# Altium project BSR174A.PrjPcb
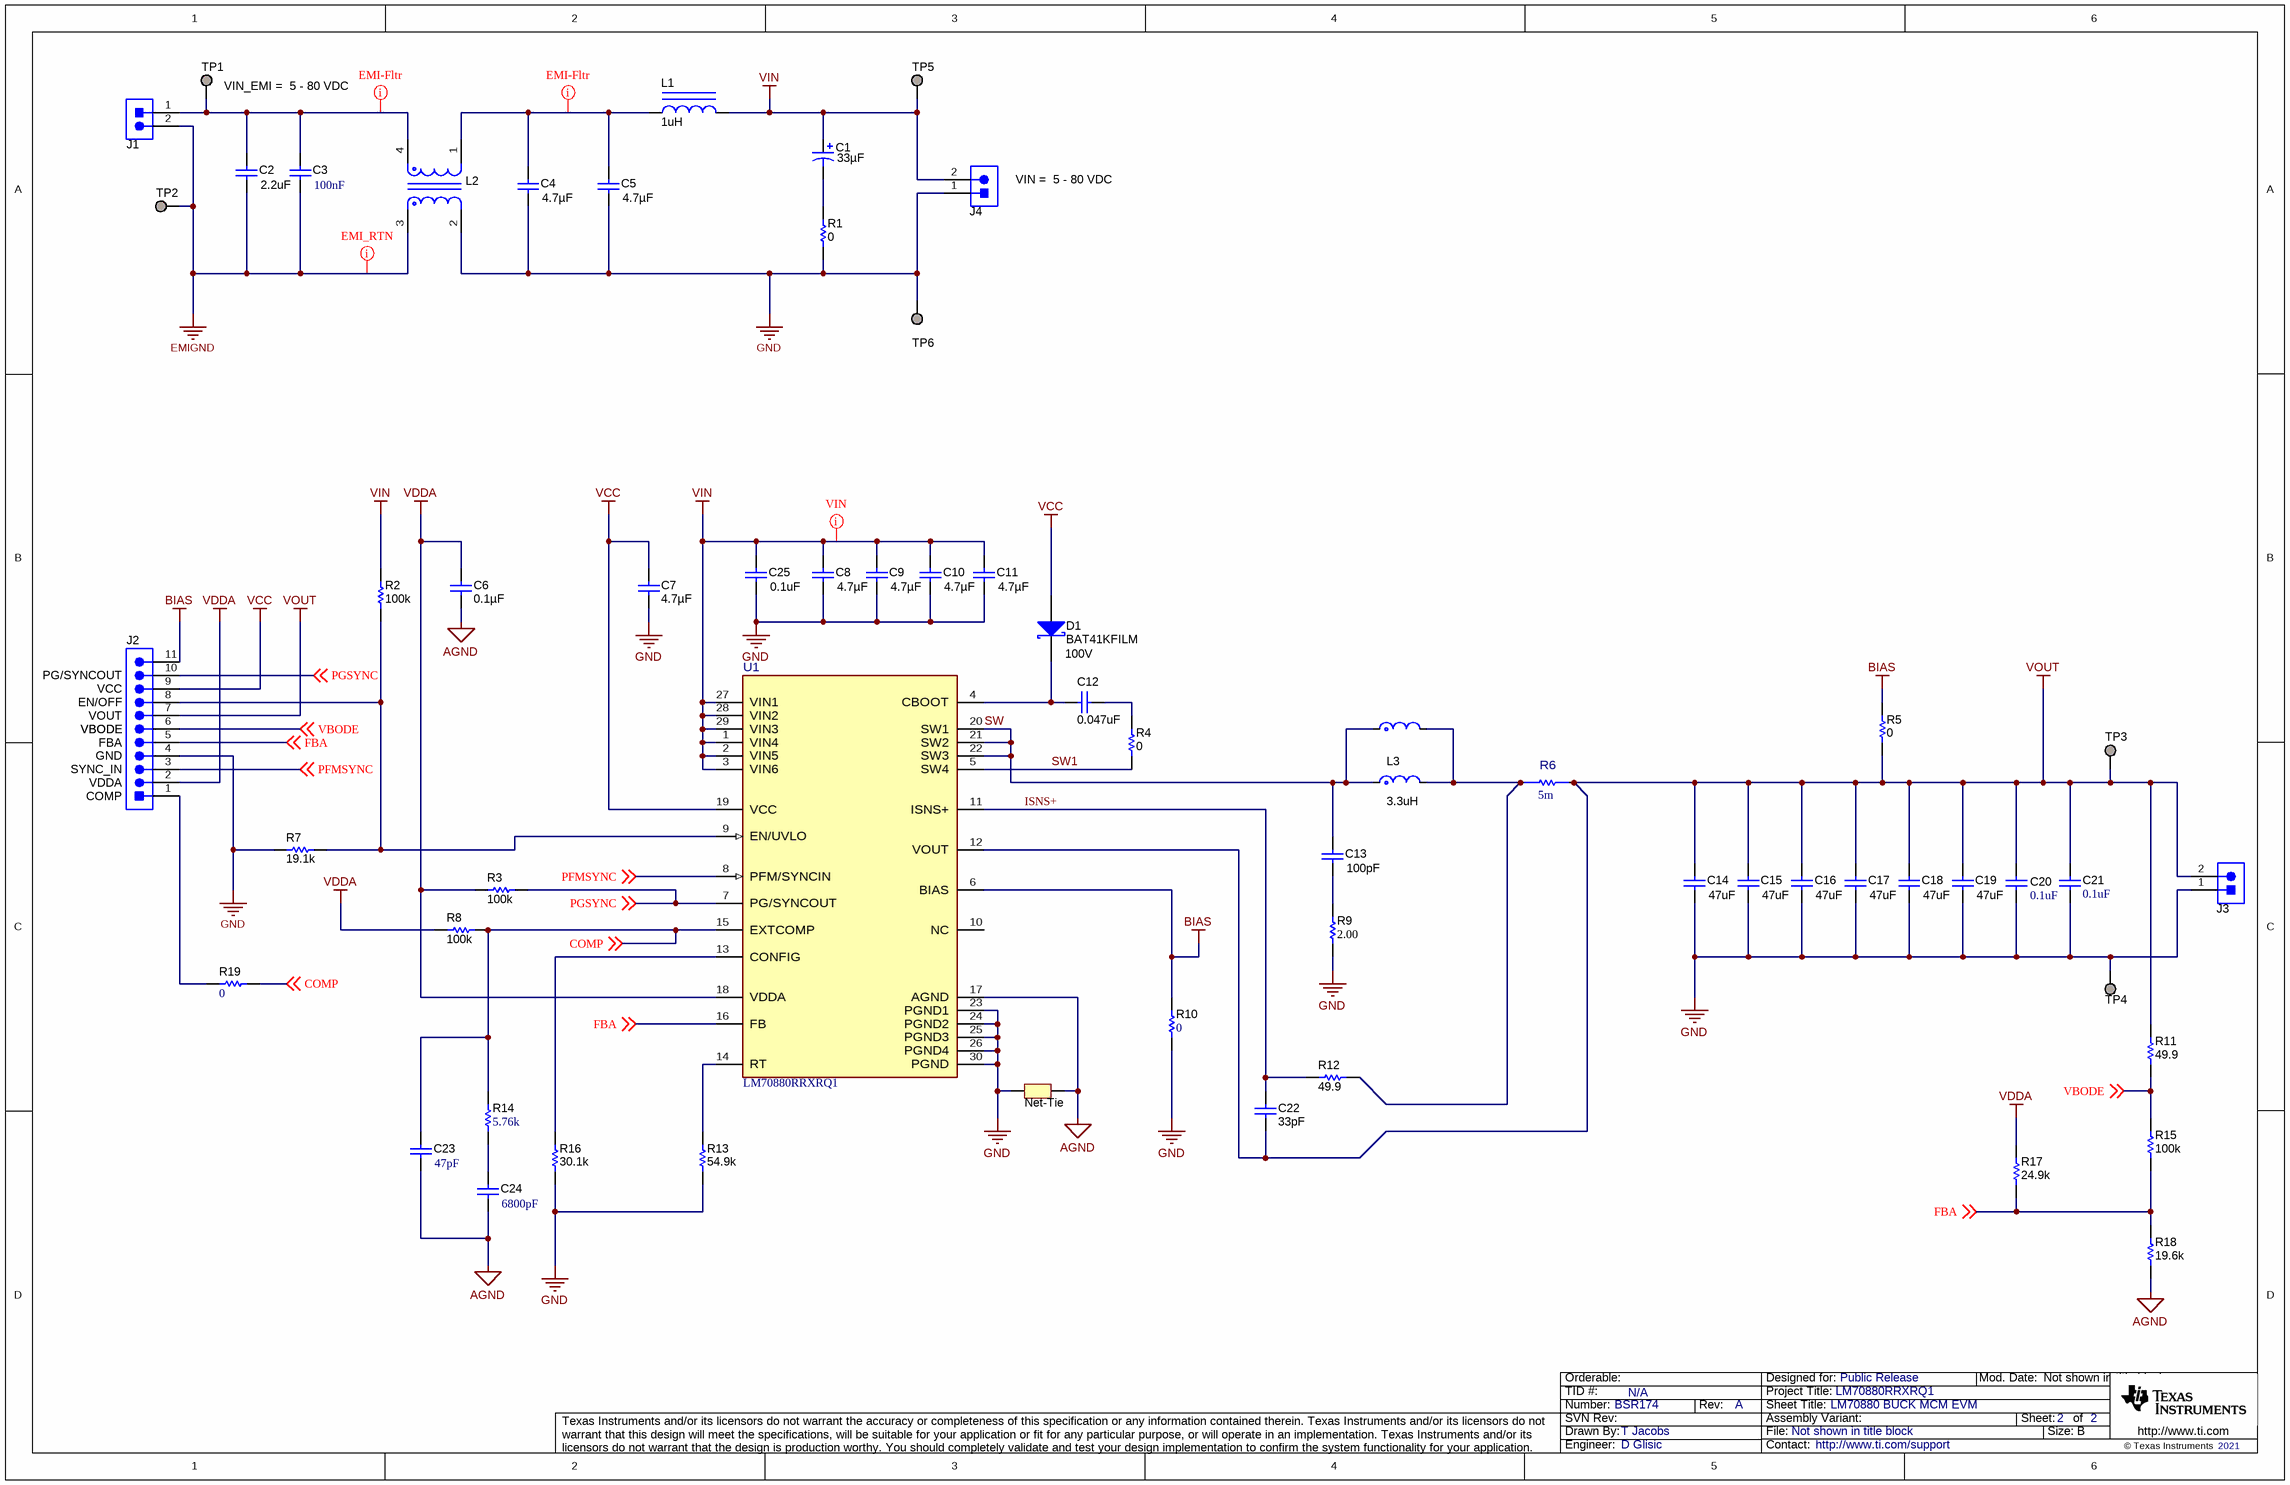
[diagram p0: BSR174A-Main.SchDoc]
CopyrightYear: 2021; PCB_Layout: T Jacobs; PCB_Rev: A; PRJ_Customer: Public Release; PRJ_Engineer: D Glisic; PRJ_Number: BSR174; PRJ_Title: LM70880RRXRQ1; SCH_Rev: A; SCH_Title: LM70880RRXRQ1; TechSupport: http://www.ti.com/support; TID: N/A
2 sheets, 89 parts. Net scope: global (net labels, ports and power ports of the same name join across sheets).
Board file: BSR174A.PcbDoc
Sheets:
  BSR174A-Main.SchDoc
  BSR174A-Hardware.SchDoc

## Sheet BSR174A-Main.SchDoc: LM70880 BUCK MCM EVM
size 431 x 279 mm; Date: Not shown in title block; ApprovedBy: Not shown in title block; CheckedBy: Not shown in title block; Author: Not shown in title block; CompanyName: Not shown in title block; DrawnBy: T Jacobs; Engineer: Not shown in title block; Organization: Not shown in title block; Address1: Not shown in title block; Address2: Not shown in title block; Address3: Not shown in title block; Address4: Not shown in title block; DocumentNumber: 2; Revision: Use project parameter SCH_Rev; SheetNumber: 2; SheetTotal: 2; PageSetup: Record=PageOptions¦CenterHorizontal=True¦CenterVertical=True¦PrintScale=1.00¦XCorrection=1.00¦YCorrection=1.00¦PrintKind=0¦BorderSize=5000000¦LeftOffset=0¦BottomOffset=0¦Orientation=2¦PaperLength=1000¦PaperWidth=1000¦Scale=100¦PaperSource=15¦PrintQuality=600¦MediaType=1¦DitherType=10¦PaperKind=Letter¦PrintScaleMode=1

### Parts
C1  ValueDisplayed: 33µF  [TG_V_1000x1020]  (hidden comment: EEE-TG2A330P)
C2  ValueDisplayed: 2.2uF  [1206_180L]  (hidden comment: CGA5L3X7S2A225K160AB)
C3  Cap_F: 100nF  [0603L]  (hidden comment: GCJ188R72A104KA01D)
C4  ValueDisplayed: 4.7µF  [1210_220L]  (hidden comment: GCM32DC72A475KE02L)
C5  ValueDisplayed: 4.7µF  [1210_220L]  (hidden comment: GCM32DC72A475KE02L)
C6  ValueDisplayed: 0.1µF  [0402L]  (hidden comment: C0402C104K8RACAUTO)
C7  Cap_F: 4.7µF  [0603L]  (hidden comment: GRM188Z71A475ME15D)
C8  ValueDisplayed: 4.7µF  [1210_220L]  (hidden comment: GCM32DC72A475KE02L)
C9  ValueDisplayed: 4.7µF  [1210_220L]  (hidden comment: GCM32DC72A475KE02L)
C10  ValueDisplayed: 4.7µF  [1210_220L]  (hidden comment: GCM32DC72A475KE02L)
C11  ValueDisplayed: 4.7µF  [1210_220L]  (hidden comment: GCM32DC72A475KE02L)
C12  ValueDisplayed: 0.047uF  [0402L]  (hidden comment: GRM155R71E473KA88D)
C13  ValueDisplayed: 100pF  [0603L]  (hidden comment: GRM1885C2A101JA01D)
C14  ValueDisplayed: 47uF  [1210_270L]  (hidden comment: GRM32ER71A476KE15L)
C15  ValueDisplayed: 47uF  [1210_270L]  (hidden comment: GRM32ER71A476KE15L)
C16  ValueDisplayed: 47uF  [1210_270L]  (hidden comment: GRM32ER71A476KE15L)
C17  ValueDisplayed: 47uF  [1210_270L]  (hidden comment: GRM32ER71A476KE15L)
C18  ValueDisplayed: 47uF  [1210_270L]  (hidden comment: GRM32ER71A476KE15L)
C19  ValueDisplayed: 47uF  [1210_270L]  (hidden comment: GRM32ER71A476KE15L)
C20  value 0.1uF  [0603L]  (hidden comment: CGA3E2X7R1H104K080AA)
C21  ValueDisplayed: 0.1uF  [0603L]  (hidden comment: CGA3E2X7R1H104K080AA)
C22  ValueDisplayed: 33pF  [0402L]  (hidden comment: GCM1555C1H330JA16D)
C23  ValueDisplayed: 47pF  [0402L]  (hidden comment: CGA2B2C0G1H470J050BA)
C24  ValueDisplayed: 6800pF  [0402L]  (hidden comment: CGA2B2X7R1H682K050BA)
C25  value 0.1uF  [0603L]  (hidden comment: GCJ188R72A104KA01D)
D1  BAT41KFILM  value 100V  [SOD-523]
J1  Header_2x1  [Phoenix_1729018]  (value not drawn)
J2  TSW-111-07-G-S  [TSW-111-07-G-S]  (value not drawn)
J3  Header_2x1  [Phoenix_1729018]  (value not drawn)
J4  1729018  [Phoenix_1729018]  (value not drawn)
L1  ValueDisplayed: 1uH  [WE-MAPI_4020]  (hidden comment: 74438356010)
L2  CM7060P701R-10  [FP-CM7060P701R-10_SMT_CMC_7MM0_6MM0-MFG]  (value not drawn)
L3  value 3.3uH  [FP-XGL6060-332MEC_SMT_6MM51_6MM71-MFG]  (hidden comment: XGL6060-332MEC)
L4  XGL1060-332MEC  [FP-XGL1060-332MEC_SMT2_10MM0_11MM3-MFG]  (value not drawn)
NT1  Net-Tie  [Net-Tie_10milWide_30milLong]  (net tie, no BOM)
R1  ValueDisplayed: 0  [0805L]  (hidden comment: ERJ-6GEY0R00V)
R2  ValueDisplayed: 100k  [0603L]  (hidden comment: CRCW0603100KFKEA)
R3  ValueDisplayed: 100k  [0402L]  (hidden comment: RMCF0402FT100K)
R4  ValueDisplayed: 0  [0402L]  (hidden comment: CRCW04020000Z0EDHP)
R5  ValueDisplayed: 0  [0402L]  (hidden comment: CRCW04020000Z0EDHP)
R6  Res_ohm: 5m  [FP-KRL2012E-M-R005-F-T5_0805_WIDE-MFG]  (hidden comment: KRL2012E-M-R005-F-T5)
R7  ValueDisplayed: 19.1k  [0402L]  (hidden comment: CRCW040219K1FKED)
R8  ValueDisplayed: 100k  [0402L]  (hidden comment: RMCF0402FT100K)
R9  ValueDisplayed: 2.00  [0603L]  (hidden comment: CRCW06032R00FKEA)
R10  ValueDisplayed: 0  [0603L]  (hidden comment: CRCW06030000Z0EA)
R11  ValueDisplayed: 49.9  [0402L]  (hidden comment: CRCW040249R9FKED)
R12  ValueDisplayed: 49.9  [0402L]  (hidden comment: CRCW040249R9FKED)
R13  ValueDisplayed: 54.9k  [0402L]  (hidden comment: CRCW040254K9FKED)
R14  ValueDisplayed: 5.76k  [0402L]  (hidden comment: CRCW04025K76FKED)
R15  ValueDisplayed: 100k  [0402L]  (hidden comment: CRCW0402100KFKED)
R16  ValueDisplayed: 30.1k  [0402L]  (hidden comment: CRCW040230K1FKED)
R17  ValueDisplayed: 24.9k  [0402L]  (hidden comment: CRCW040224K9FKED)
R18  ValueDisplayed: 19.6k  [0402L]  (hidden comment: CRCW040219K6FKED)
R19  ValueDisplayed: 0  [0402L]  (hidden comment: CRCW04020000Z0ED)
TP1  5019  [Keystone_5019]  (value not drawn)
TP2  5019  [Keystone_5019]  (value not drawn)
TP3  5019  [Keystone_5019]  (value not drawn)
TP4  5019  [Keystone_5019]  (value not drawn)
TP5  5019  [Keystone_5019]  (value not drawn)
TP6  5019  [Keystone_5019]  (value not drawn)
U1  LM70880RRXRQ1  [RRX0029B-MFG]

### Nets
AGND: C6.1 C23.2 C24.2 NT1.2 R18.1 U1.17(AGND)
BIAS: J2.11 R5.2 R10.2 U1.6(BIAS)
EMIGND: C2.2 C3.2 J1.2 L2.3 TP2.1
GND: C4.2 C5.2 C7.2 C8.2 C9.2 C10.2 C11.2 C14.2 C15.2 C16.2 C17.2 C18.2 C19.2 C20.2 C21.2 C25.2 J2.4 J3.1 J4.1 L2.2 NT1.1 R1.1 R7.1 R9.2 R10.1 R13.2 R16.1 TP4.1 TP6.1 U1.23(PGND1) U1.24(PGND2) U1.25(PGND3) U1.26(PGND4) U1.30(PGND)
VCC: C7.1 D1.2(A) J2.9 U1.19(VCC)
VDDA: C6.2 J2.2 R3.2 R8.2 R17.2 U1.18(VDDA)
VIN: C1.1(+) C8.1 C9.1 C10.1 C11.1 C25.1 J4.2 L1.2 R2.2 TP5.1 U1.1(VIN4) U1.2(VIN5) U1.3(VIN6) U1.27(VIN1) U1.28(VIN2) U1.29(VIN3)
VOUT: C14.1 C15.1 C16.1 C17.1 C18.1 C19.1 C20.1 C21.1 C22.1 J2.7 J3.2 R5.1 R6.2 R11.2 TP3.1 U1.12(VOUT)
COMP: C23.1 R8.1 R14.2 R19.2 U1.15(EXTCOMP) ; off-sheet COMP
CONFIG: R16.2 U1.13(CONFIG)
EN/UVLO: J2.8 R2.1 R7.2 U1.9(EN/UVLO)
FBA: J2.5 R15.1 R17.1 R18.2 U1.16(FB) ; off-sheet FBA
ISNS+: C22.2 R12.1 U1.11(ISNS+)
PFMSYNC: J2.3 U1.8(PFM/SYNCIN) ; off-sheet PFMSYNC
PGSYNC: J2.10 R3.1 U1.7(PG/SYNCOUT) ; off-sheet PGSYNC
RT: R13.1 U1.14(RT)
SW: C13.1 L3.1 L4.1 U1.20(SW1) U1.21(SW2) U1.22(SW3)
SW1: R4.1 U1.5(SW4)
VBODE: J2.6 R11.1 R15.2 ; off-sheet VBODE
NetC1_2: C1.2(-) R1.2
NetC2_1: C2.1 C3.1 J1.1 L2.4 TP1.1
NetC4_1: C4.1 C5.1 L1.1 L2.1
NetC12_1: C12.1 D1.1(K) U1.4(CBOOT)
NetC12_2: C12.2 R4.2
NetC13_2: C13.2 R9.1
NetC24_1: C24.1 R14.1
NetJ2_1: J2.1 R19.1
NetL3_2: L3.2 L4.2 R6.1 R12.2

Not connected (* = marked no-connect by the designer): U1 10(NC)

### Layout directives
EMI-Flt: EMI-Flt; rule Clearance Constraint [Clearance = 24mil]; rule Undefined: NetC2_1, NetC4_1
rule Clearance Constraint [Clearance = 24mil]: EMIGND
mark named VIN: VIN

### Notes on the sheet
- (near TP1) VIN_EMI =  5 - 80 VDC
- (near J4) VIN =  5 - 80 VDC
- (near J2) PG/SYNCOUT
- (near J2) EN/OFF
- (near J2) VCC
- (near J2) SYNC_IN
- (near J2) VBODE
- (near J2) VOUT
- (near J2) GND
- (near J2) FBA
- (near J2) COMP
- (near J2) VDDA

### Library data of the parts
C1 = CMP-0086185-1: CAP, AL, 33 µF, 100 V, +/- 20%, 1 ohm, AEC-Q200 Grade 1, SMD; Manufacturer: Panasonic; TaMin_C: -40°C; ESR_ohm: 1; Polarized: Y; SizeAreaWB_mm2: 151.29; Value1: 1 ohm; U/M: EA; Value: 33uF; TaMax_C: 125°C; SizeZ_mm: 10.5; SizeX_mm: 10.3; Cap_Case: 10x10.2mm; Value2: 100V; SizeArea_mm2: 106.09; CompType: Capacitor; AEC Category: Q200
C2 = CMP-0008790-2: CAP, CERM, 2.2 uF, 100 V, +/- 10%, X7S, AEC-Q200 Grade 1, 1206; Manufacturer: TDK; TaMin_C: -55°C; ESR_ohm: 5.718m; Polarized: N; SizeAreaWB_mm2: 10.92; Value1: 0.005718 ohm; U/M: EA; Value: 2.2uF; TaMax_C: 125°C; SizeZ_mm: 1.8; SizeX_mm: 3.2; SizeY_mm: 1.6; Cap_Case: 1206_180; Value2: 100V; SizeArea_mm2: 5.12; AEC Qualified: Y; Cap_F: 2.2µF; IRMS_A: 3.0363A; AEC Grade: 1; AEC Category: Q200
C3 = CMP-0064935-4: CAP, CERM, 0.1 uF, 100 V,+/- 10%, X7R, AEC-Q200 Grade 1, 0603; Manufacturer: MuRata; TaMin_C: -55°C; Polarized: N; SizeAreaWB_mm2: 4.68; U/M: EA; Value: 0.1uF; TaMax_C: 125°C; SizeZ_mm: 1; SizeX_mm: 1.6; SizeY_mm: 0.8; Cap_Case: 0603; Value2: 100V; SizeArea_mm2: 1.28; AEC Qualified: Y; AEC Category: Q200; Value1: Unknown
C4 C5 C8-C11 = CMP-0082268-1: CAP, CERM, 4.7 µF, 100 V,+/- 10%, X7S, AEC-Q200 Grade 1, 1210; Manufacturer: MuRata; TaMin_C: -55°C; ESR_ohm: 1m; Polarized: N; SizeAreaWB_mm2: 14.7; Value1: 0.001 ohm; U/M: EA; Value: 4.7uF; TaMax_C: 125°C; SizeZ_mm: 2.2; SizeX_mm: 3.2; SizeY_mm: 2.5; Cap_Case: 1210; Value2: 100V; SizeArea_mm2: 8; AEC Qualified: Y; IRMS_A: 6A; AEC Grade: 1; AEC Category: Q200
C6 = CMP-0079150-1: CAP, CERM, 0.1 µF, 10 V,+/- 10%, X7R, AEC-Q200 Grade 1, 0402; Manufacturer: Kemet; Polarized: N; Value: 0.1uF; U/M: EA; Cap_F: 100nF; VDC_V: 10V; TaMin_C: -55°C; TaMax_C: 125°C; Cap_Case: 0402; AEC Category: Q200; AEC Grade: 1; AEC Qualified: Y; SizeArea_mm2: 0.5; SizeAreaWB_mm2: 3; SizeZ_mm: 0.6
C7 = CMP-0007498-4: CAP, CERM, 4.7 uF, 10 V, +/- 20%, X7R, 0603; Manufacturer: MuRata; Polarized: N; Value: 4.7uF; U/M: EA; Value1: Unknown; VDC_V: 10V; TaMin_C: -55°C; TaMax_C: 125°C; Cap_Case: 0603; AEC Category: Q200; SizeArea_mm2: 1.28; SizeAreaWB_mm2: 4.68; SizeX_mm: 1.6; SizeY_mm: 0.8; SizeZ_mm: 1
C12 = CMP-0006669-2: CAP, CERM, 0.047 uF, 25 V, +/- 10%, X7R, 0402; Manufacturer: MuRata; Polarized: N; U/M: EA; Cap_F: 47nF; Value1: Unknown; VDC_V: 25V; TaMin_C: -55°C; TaMax_C: 125°C; Cap_Case: 0402; AEC Category: Q200; SizeArea_mm2: 0.5; SizeAreaWB_mm2: 3; SizeX_mm: 1; SizeZ_mm: 0.6
C13 = CMP-0007237-4: CAP, CERM, 100 pF, 100 V, +/- 5%, C0G/NP0, 0603; Manufacturer: MuRata; TaMin_C: -55°C; Polarized: N; SizeAreaWB_mm2: 4.68; Value1: Unknown; U/M: EA; Value: 100pF; TaMax_C: 125°C; SizeZ_mm: 1; SizeX_mm: 1.6; SizeY_mm: 0.8; Cap_Case: 0603; Value2: 100V; SizeArea_mm2: 1.28; AEC Category: Q200
C14-C19 = CMP-0009220-2: CAP, CERM, 47 uF, 10 V, +/- 10%, X7R, 1210; Manufacturer: MuRata; TaMin_C: -55°C; Polarized: N; SizeAreaWB_mm2: 14.7; Value1: Unknown; U/M: EA; Value: 47uF; TaMax_C: 125°C; SizeZ_mm: 2.7; SizeX_mm: 3.2; SizeY_mm: 2.5; Cap_Case: 1210; Value2: 10V; SizeArea_mm2: 8; Cap_F: 47µF; AEC Category: Q200
C20 = CMP-0007078-4: CAP, CERM, 0.1 uF, 50 V, +/- 10%, X7R, AEC-Q200 Grade 1, 0603; Manufacturer: TDK; TaMin_C: -55°C; Polarized: N; SizeAreaWB_mm2: 4.68; Value1: 0.0296 ohm; U/M: EA; TaMax_C: 125°C; SizeZ_mm: 1; SizeX_mm: 1.6; SizeY_mm: 0.8; Cap_Case: 0603; Value2: 50V; SizeArea_mm2: 1.28; AEC Qualified: Y; Cap_F: 100nF; AEC Category: Q200; ESR_ohm: 29.6m; IRMS_A: 971.99mA
C21 = CMP-0007078-4: CAP, CERM, 0.1 uF, 50 V, +/- 10%, X7R, AEC-Q200 Grade 1, 0603; Manufacturer: TDK; Polarized: N; Value: 0.1uF; U/M: EA; Cap_F: 100nF; ESR_ohm: 29.6m; Value1: 0.0296 ohm; VDC_V: 50V; IRMS_A: 971.99mA; TaMin_C: -55°C; TaMax_C: 125°C; Cap_Case: 0603; AEC Category: Q200; AEC Grade: 1; AEC Qualified: Y; SizeArea_mm2: 1.28; SizeAreaWB_mm2: 4.68; SizeX_mm: 1.6; SizeY_mm: 0.8
C22 = CMP-0860833-1: CAP, CERM, 33 pF, 50 V,+/- 5%, C0G/NP0, AEC-Q200 Grade 1, 0402; Manufacturer: MuRata; Polarized: N; Value: 33pF; U/M: EA; VDC_V: 50V; TaMin_C: -55°C; TaMax_C: 125°C; Cap_Case: 0402; AEC Category: Q200; AEC Grade: 1; AEC Qualified: Y; SizeArea_mm2: 0.5; SizeAreaWB_mm2: 3; SizeZ_mm: 0.6
C23 = CMP-0860832-1: CAP, CERM, 47 pF, 50 V,+/- 5%, C0G/NP0, AEC-Q200 Grade 1, 0402; Manufacturer: TDK; TaMin_C: -55°C; Polarized: N; SizeAreaWB_mm2: 3; U/M: EA; Value: 47pF; TaMax_C: 125°C; SizeZ_mm: 0.6; SizeX_mm: 1; SizeY_mm: 0.5; Cap_Case: 0402; Value2: 50V; AEC Qualified: Y; AEC Category: Q200
C24 = CMP-0006323-2: CAP, CERM, 6800 pF, 50 V, +/- 10%, X7R, AEC-Q200 Grade 1, 0402; Manufacturer: TDK; TaMin_C: -55°C; Polarized: N; SizeAreaWB_mm2: 3; Value1: 0.391597 ohm; U/M: EA; Value: 6800pF; TaMax_C: 125°C; SizeZ_mm: 0.6; SizeX_mm: 1; SizeY_mm: 0.5; Cap_Case: 0402; Value2: 50V; AEC Qualified: Y; Cap_F: 6.8nF; AEC Category: Q200; ESR_ohm: 0.3916; IRMS_A: 315.526mA
C25 = CMP-0064935-4: CAP, CERM, 0.1 uF, 100 V,+/- 10%, X7R, AEC-Q200 Grade 1, 0603; Manufacturer: MuRata; TaMin_C: -55°C; Polarized: N; SizeAreaWB_mm2: 4.68; Value1: Unknown; U/M: EA; TaMax_C: 125°C; SizeZ_mm: 1; SizeX_mm: 1.6; SizeY_mm: 0.8; Cap_Case: 0603; Value2: 100V; SizeArea_mm2: 1.28; AEC Qualified: Y; Cap_F: 100nF; AEC Category: Q200
D1 = CMP-0028894-3: Diode, Schottky, 100 V, 0.2 A, SOD-523; Manufacturer: STMicroelectronics; SizeZ_mm: 0.65; Vf_V: 1V; SizeArea_mm2: 1.53; AEC Qualified: N; TJmax_C: 150°C; SizeX_mm: 1.7; SizeY_mm: 0.9; Value1: 0.2A; Green_REACh: Incomplete; SizeAreaWB_mm2: 5.13; Green_Lifecycle: Not Set; Io_A: 200mA; AEC Category: Q101
J1 J3 = CMP-0055486-1: TERM BLOCK 2POS 5mm, TH; PartNumber: 1729018; Manufacturer: Phoenix Contact; CompType: Terminal Block; CNHeader: FALSE; CT: TRUE; Green_Lifecycle: Not Set; Green_REACh: Incomplete
J2 = CMP-0075454-1: Header, 100mil, 11x1, Gold, TH; Manufacturer: Samtec; Pitch_mm: 2.54; Cert_VDE: N; Gender: Male; Cert_CSA: Y; Voltage_V: 550V; Green_REACh: Passed; Current_A: 6.3A; CT: False; Green_Lifecycle: Active; Row_Count: 1; CNHeader: True
J4 = CMP-0055486-1: TERM BLOCK 2POS 5mm, TH; Manufacturer: Phoenix Contact; CT: TRUE; Green_REACh: Incomplete; CompType: Terminal Block; CNHeader: FALSE; Green_Lifecycle: Not Set
L1 = CMP-0064168-1: Inductor, Shielded, 1 uH, 7.2 A, 0.012 ohm, SMD; Manufacturer: Wurth Elektronik; Isat: 9A @ 20% inductance drop; Irms: 7.2A @ 40C rise; Green_Lifecycle: Active; SizeAreaWB_mm2: 26.01; DCR_ohm: 12m; Green_REACh: Passed; Value: 1uH; Imax_A: 7.2A; SizeZ_mm: 2.1; SizeX_mm: 4.1; SizeArea_mm2: 16.81; Ind_H: 1µH; AEC Qualified: N; AEC Category: Q200
L2 = CMP-0094039-1: Common Mode Choke Power 700Ω 4A -40 to 125°C Wire Wound Surface Mount T/R; Manufacturer: Laird; AEC Qualified: No; DCR_ohm: 15m; SizeZ_mm: 3.8mm; Impedance At Frequency: 700Ω @ 100MHz
L3 = CMP-0093175-1: Shielded Power Inductors 3.3uH 20% tol, 6.5mOhm 16.6A; Manufacturer: Coilcraft; Isat: 6.6A; DCR_ohm: 6.5m; Material: Composite; SizeZ_mm: 6.1mm; Ind_H: 3.3µH; AEC Qualified: Yes; AEC Grade: Grade 1; TaMax_C: +125°C; Test Frequency: 1MHz; Shrouded: true; TaMin_C: -40°C; Self Resonant Frequency: 24MHz
L4 = CMP-0097455-1: Shielded Power Inductors 3.3uH 22A 5.7mOhm; Manufacturer: Coilcraft; Isat: 10.9A; DCR_ohm: 5.7m; Ind_H: 3.3µH; Self Resonant Frequency: 21MHz; AEC Grade: Grade 1; SizeZ_mm: 6mm; Tolerance_%: 20%; TaMax_C: +125°C; AEC Qualified: Yes; TaMin_C: -40°C; Test Frequency: 1MHz; Material: Composite; Shrouded: true
NT1 = CMP-0078142-6: Single point connection between nets.
R1 = CMP-0020616-3: RES, 0, 5%, 0.125 W, AEC-Q200 Grade 0, 0805; Manufacturer: Panasonic; Value: 0; Value_Code: 0000; Power_W: 125mW; Value2: 0.125W; VDC_V: 150V; TempCo: 600 ppm/C; EIA_Code: E24; AEC Category: Q200; AEC Qualified: Y; SizeArea_mm2: 2.5; SizeX_mm: 2; SizeY_mm: 1.25; SizeZ_mm: 1.45; SizeAreaWB_mm2: 6.75
R2 = CMP-0021990-4: RES, 100 k, 1%, 0.1 W, AEC-Q200 Grade 0, 0603; Manufacturer: Vishay-Dale; Power_W: 100mW; TempCo: 100 ppm/C; Value: 100k; EIA_Code: E96; SizeX_mm: 1.6; SizeY_mm: 0.8; SizeZ_mm: 1; Value2: 0.1W; SizeArea_mm2: 1.28; AEC Qualified: Y; VDC_V: 75V; AEC Category: Q200; AEC Grade: 0
R3 R8 = CMP-0026753-1: RES, 100 k, 1%, 0.063 W, AEC-Q200 Grade 0, 0402; Manufacturer: Stackpole Electronics Inc; Value: 100k; Power_W: 63mW; Value2: 0.063W; VDC_V: 50V; TempCo: 100 ppm/C; EIA_Code: E96; AEC Category: Q200; AEC Grade: 0; AEC Qualified: Y; SizeArea_mm2: 0.5; SizeX_mm: 1; SizeZ_mm: 0.6; U/M: EA
R4 = CMP-0081856-1: RES, 0, 0%, 0.2 W, AEC-Q200 Grade 0, 0402; Manufacturer: Vishay-Dale; SizeAreaWB_mm2: 3; SizeArea_mm2: 0.5; AEC Qualified: Y; AEC Category: Q200; Value: 0; SizeZ_mm: 0.6; Power_W: 200mW; VDC_V: 50V; Value2: 0.2W; SizeX_mm: 1
R5 = CMP-0081856-1: RES, 0, 0%, 0.2 W, AEC-Q200 Grade 0, 0402; Manufacturer: Vishay-Dale; Value: 0; Power_W: 200mW; Value2: 0.2W; VDC_V: 50V; AEC Category: Q200; AEC Qualified: Y; SizeArea_mm2: 0.5; SizeX_mm: 1; SizeZ_mm: 0.6; SizeAreaWB_mm2: 3
R6 = CMP-0090651-1: 5 mOhms ±1% 1W Chip Resistor Wide 0805 (2012 Metric), 0508 Automotive AEC-Q200, Current Sense Metal Foil; Manufacturer: Susumu; TempCo: 50ppm/°C; AEC Grade: Grade 0; AEC Qualified: Yes; SizeZ_mm: 0.7mm; Value: 5m
R7 = CMP-0026067-3: RES, 19.1 k, 1%, 0.063 W, AEC-Q200 Grade 0, 0402; Manufacturer: Vishay-Dale; Power_W: 63mW; TempCo: 100 ppm/C; Value_Code: 19k1; Value: 19.1k; EIA_Code: E96; SizeX_mm: 1; SizeY_mm: 0.5; SizeZ_mm: 0.6; Value2: 0.063W; AEC Qualified: Y; VDC_V: 50V; AEC Category: Q200; AEC Grade: 0
R9 = CMP-0022302-4: RES, 2.00, 1%, 0.1 W, AEC-Q200 Grade 0, 0603; Manufacturer: Vishay-Dale; Power_W: 100mW; TempCo: 100 ppm/C; Value_Code: 2R00; Value: 2.00; EIA_Code: E96; Res_ohm: 2; SizeX_mm: 1.6; SizeY_mm: 0.8; SizeZ_mm: 1; Value2: 0.1W; SizeArea_mm2: 1.28; AEC Qualified: Y; VDC_V: 75V; AEC Category: Q200; AEC Grade: 0
R10 = CMP-0025697-4: RES, 0, 5%, 0.1 W, AEC-Q200 Grade 0, 0603; Manufacturer: Vishay-Dale; Power_W: 100mW; TempCo: 200 ppm/C; Value_Code: 0000; Value: 0; EIA_Code: E24; SizeX_mm: 1.6; SizeY_mm: 0.8; SizeZ_mm: 1; Value2: 0.1W; SizeArea_mm2: 1.28; AEC Qualified: Y; AEC Category: Q200; VDC_V: 75V
R11 = CMP-0026404-2: RES, 49.9, 1%, 0.063 W, AEC-Q200 Grade 0, 0402; Manufacturer: Vishay-Dale; Value: 49.9; Value_Code: 49R9; Power_W: 63mW; Value2: 0.063W; VDC_V: 50V; TempCo: 100 ppm/C; EIA_Code: E96; AEC Category: Q200; AEC Grade: 0; AEC Qualified: Y; SizeArea_mm2: 0.5; SizeX_mm: 1; SizeZ_mm: 0.6
R12 = CMP-0026404-2: RES, 49.9, 1%, 0.063 W, AEC-Q200 Grade 0, 0402; Manufacturer: Vishay-Dale; Value_Code: 49R9; SizeArea_mm2: 0.5; AEC Qualified: Y; AEC Category: Q200; Value: 49.9; SizeZ_mm: 0.6; AEC Grade: 0; Power_W: 63mW; VDC_V: 50V; Value2: 0.063W; SizeX_mm: 1; EIA_Code: E96; TempCo: 100 ppm/C
R13 = CMP-0026449-2: RES, 54.9 k, 1%, 0.063 W, AEC-Q200 Grade 0, 0402; Manufacturer: Vishay-Dale; Power_W: 63mW; TempCo: 100 ppm/C; Value_Code: 54k9; Value: 54.9k; EIA_Code: E96; SizeX_mm: 1; SizeY_mm: 0.5; SizeZ_mm: 0.6; Value2: 0.063W; AEC Qualified: Y; VDC_V: 50V; AEC Category: Q200; AEC Grade: 0
R14 = CMP-0026468-2: RES, 5.76 k, 1%, 0.063 W, AEC-Q200 Grade 0, 0402; Manufacturer: Vishay-Dale; Power_W: 63mW; TempCo: 100 ppm/C; Value_Code: 5k76; Value: 5.76k; EIA_Code: E96; SizeX_mm: 1; SizeY_mm: 0.5; SizeZ_mm: 0.6; Value2: 0.063W; AEC Qualified: Y; VDC_V: 50V; AEC Category: Q200; AEC Grade: 0
R15 = CMP-0025950-3: RES, 100 k, 1%, 0.063 W, AEC-Q200 Grade 0, 0402; Manufacturer: Vishay-Dale; Power_W: 63mW; TempCo: 100 ppm/C; Value: 100k; EIA_Code: E96; SizeX_mm: 1; SizeY_mm: 0.5; SizeZ_mm: 0.6; Value2: 0.063W; AEC Qualified: Y; VDC_V: 50V; AEC Category: Q200; AEC Grade: 0
R16 = CMP-0026284-2: RES, 30.1 k, 1%, 0.063 W, AEC-Q200 Grade 0, 0402; Manufacturer: Vishay-Dale; Power_W: 63mW; TempCo: 100 ppm/C; Value_Code: 30k1; Value: 30.1k; EIA_Code: E96; SizeX_mm: 1; SizeY_mm: 0.5; SizeZ_mm: 0.6; Value2: 0.063W; AEC Qualified: Y; VDC_V: 50V; AEC Category: Q200; AEC Grade: 0
R17 = CMP-0026196-2: RES, 24.9 k, 1%, 0.063 W, AEC-Q200 Grade 0, 0402; Manufacturer: Vishay-Dale; Power_W: 63mW; TempCo: 100 ppm/C; Value_Code: 24k9; Value: 24.9k; EIA_Code: E96; SizeX_mm: 1; SizeY_mm: 0.5; SizeZ_mm: 0.6; Value2: 0.063W; AEC Qualified: Y; VDC_V: 50V; AEC Category: Q200; AEC Grade: 0
R18 = CMP-0026068-3: RES, 19.6 k, 1%, 0.063 W, AEC-Q200 Grade 0, 0402; Manufacturer: Vishay-Dale; Power_W: 63mW; TempCo: 100 ppm/C; Value_Code: 19k6; Value: 19.6k; EIA_Code: E96; SizeX_mm: 1; SizeY_mm: 0.5; SizeZ_mm: 0.6; Value2: 0.063W; AEC Qualified: Y; VDC_V: 50V; AEC Category: Q200; AEC Grade: 0
R19 = CMP-0026822-3: RES, 0, 5%, 0.063 W, AEC-Q200 Grade 0, 0402; Manufacturer: Vishay-Dale; Value_Code: 0000; SizeArea_mm2: 0.5; AEC Qualified: Y; AEC Category: Q200; Value: 0; SizeZ_mm: 0.6; Power_W: 63mW; VDC_V: 50V; Value2: 0.063W; SizeX_mm: 1; EIA_Code: E24; TempCo: 200 ppm/C
TP1-TP6 = CMP-0055162-1: Test Point, Miniature, SMT; Manufacturer: Keystone; CNHeader: FALSE; Green_Lifecycle: Active; Green_REACh: Passed; CT: TRUE
U1 = CMP-0096026-3: 80-V, 8-A Synchronous DC/DC Buck Converter With Ultra-Low IQ, VQFN29; Manufacturer: Texas Instruments; Number Of Outputs: 1; Switching Frequency: 0.2-2.2MHz; SizeZ_mm: 1mm; Output Voltage: 0.8-55V; Output Type: AdjustableProgrammable; AEC Qualified: Yes; AEC Grade: Grade 1; TaMin_C: -40°C; TaMax_C: +125°C; Standoff Height: 0mm; Min Supply Voltage: 4.5V; Max Supply Voltage: 80V; TJmax_C: +150°C; CompType: IC; AEC Category: Q200

## Sheet BSR174A-Hardware.SchDoc: LM70880 Buck MCM EVM Harware
size 431 x 279 mm; Date: Not shown in title block; ApprovedBy: Not shown in title block; CheckedBy: Not shown in title block; Author: Not shown in title block; CompanyName: Not shown in title block; DrawnBy: T Jacobs; Engineer: Not shown in title block; Organization: Not shown in title block; Address1: Not shown in title block; Address2: Not shown in title block; Address3: Not shown in title block; Address4: Not shown in title block; DocumentNumber: 1; Revision: Use project parameter SCH_Rev; SheetNumber: 1; SheetTotal: 2; PageSetup: Record=PageOptions¦CenterHorizontal=True¦CenterVertical=True¦PrintScale=1.00¦XCorrection=1.00¦YCorrection=1.00¦PrintKind=0¦BorderSize=5000000¦LeftOffset=0¦BottomOffset=0¦Orientation=2¦PaperLength=1000¦PaperWidth=1000¦Scale=100¦PaperSource=15¦PrintQuality=600¦MediaType=1¦DitherType=10¦PaperKind=Letter¦PrintScaleMode=1
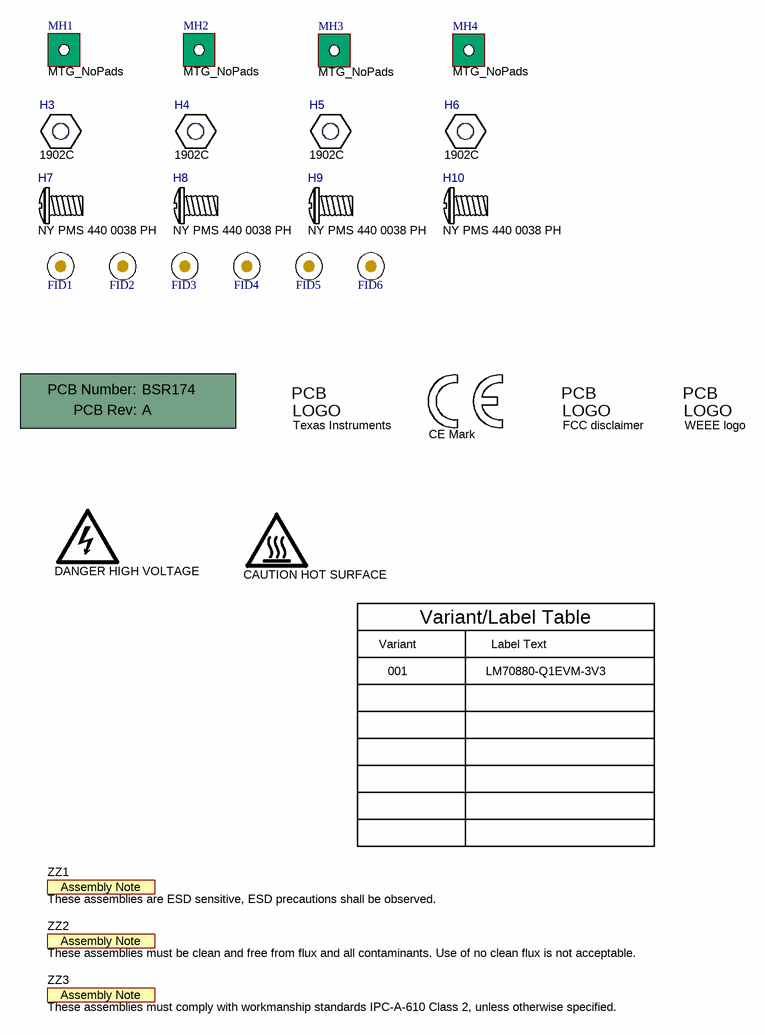
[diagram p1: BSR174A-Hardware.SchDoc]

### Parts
!PCB1  Printed Circuit Board  (value not drawn)  (mechanical)
FID1  Fiducial  [Fiducial10-20]  (value not drawn)
FID2  Fiducial  [Fiducial10-20]  (value not drawn)
FID3  Fiducial  [Fiducial10-20]  (value not drawn)
FID4  Fiducial  [Fiducial10-20]  (value not drawn)
FID5  Fiducial  [Fiducial10-20]  (value not drawn)
FID6  Fiducial  [Fiducial10-20]  (value not drawn)
H3  1902C  [Keystone_1902C]  (mechanical)
H4  1902C  [Keystone_1902C]  (mechanical)
H5  1902C  [Keystone_1902C]  (mechanical)
H6  1902C  [Keystone_1902C]  (mechanical)
H7  NY PMS 440 0038 PH  (mechanical)
H8  NY PMS 440 0038 PH  (mechanical)
H9  NY PMS 440 0038 PH  (mechanical)
H10  NY PMS 440 0038 PH  (mechanical)
Logo1  CE Mark  [CE_Mark_5mm]  (no BOM)
Logo2  Texas Instruments  [TI_Stacked_Overlay_Small]  (no BOM)
Logo3  FCC disclaimer  [FCC_disclaimer]  (no BOM)
Logo4  WEEE logo  [WEEE_Minimum]  (no BOM)
LOGO5  CAUTION HOT SURFACE  [IEC_HotSurface_Small]  (no BOM)
LOGO6  DANGER HIGH VOLTAGE  [IEC_HighVoltage_Medium]  (no BOM)
MH1  MTG_NoPads  [MTG_159mil]  (no BOM)
MH2  MTG_NoPads  [MTG_159mil]  (no BOM)
MH3  MTG_NoPads  [MTG_159mil]  (no BOM)
MH4  MTG_NoPads  [MTG_159mil]  (no BOM)
ZZ1  These assemblies are ESD sensitive, ESD precautions shall be observed.  [AssemblyNote]  (no BOM)
ZZ2  These assemblies must be clean and free from flux and all contaminants. Use of no clean flux is not acceptable.  [AssemblyNote]  (no BOM)
ZZ3  These assemblies must comply with workmanship standards IPC-A-610 Class 2, unless otherwise specified.  [AssemblyNote]  (no BOM)

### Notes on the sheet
- Variant
- Variant/Label Table
- Label Text
- 001
- LM70880-Q1EVM-3V3

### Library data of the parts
!PCB1 = CMP-0003618-2: Manufacturer: Any; PartNumber: BSR174
FID1-FID6 = CMP-0077181-1: Fiducial mark.  There is nothing to buy or mount.
H3-H6 = CMP-0003610-1: Standoff, Hex, 0.5"L #4-40 Nylon; Manufacturer: Keystone; CompType: Hardware
H7-H10 = CMP-0003667-1: Screw, Pan Head , 4-40, 3/8", Nylon; Manufacturer: B&F Fastener Supply; CompType: Hardware
Logo1 = CMP-0074844-1: SymbolCreator: a0412235
Logo2 = CMP-0074838-1: Texas Instrument Corporate Signature; SymbolCreator: a0412235; Lib Reference: TI_Logo
Logo3 = CMP-0074847-1: FCC_disclaimer
Logo4 = CMP-0074769-1
LOGO5 = CMP-0074837-2: IEC 61010-1 Hot Surface Warning; Manufacturer: Texas Instruments; SymbolCreator: a0412235; CompType: IC; AEC Category: Q200
LOGO6 = CMP-0074835-1: IEC 61010-1 High Voltage Warning; SymbolCreator: a0412235
MH1-MH4 = CMP-0078424-2: PCB Mounting Hole, No Pad; Manufacturer: Any; Key: Mounting Hole (non-standard) No Pad
ZZ1 = CMP-0077236-1
ZZ2 = CMP-0077237-1
ZZ3 = CMP-0077238-1

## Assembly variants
001: not fitted C13 C18 C19 C21 D1 FID1 FID2 FID3 FID4 FID5 FID6 L4 R5 R8 R9 R11 R15 R18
